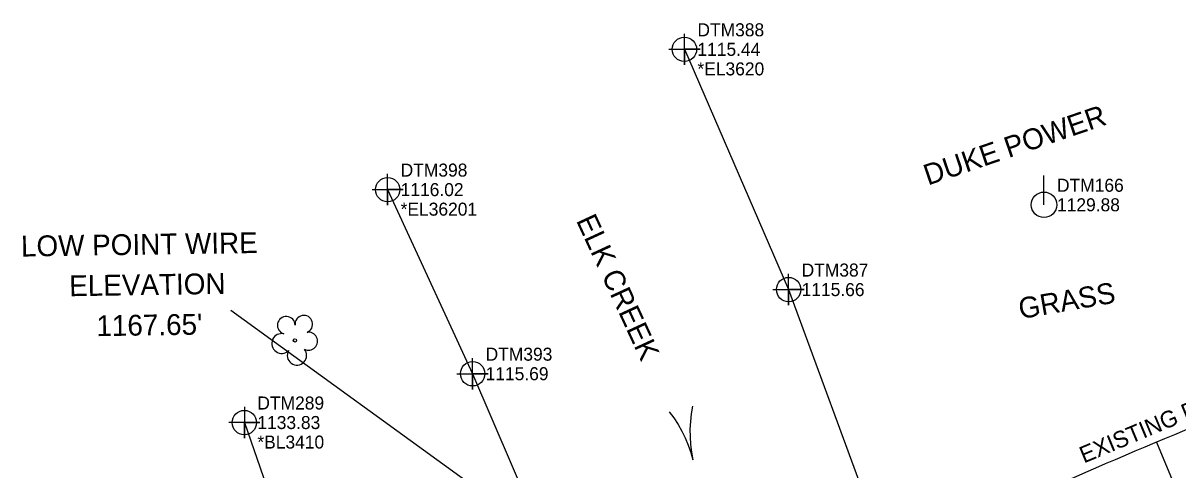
# Model space of a CAD drawing. Extents: x 1286007 to 1287145, y 857718 to 858514.
# Drawn here: x 1286461 to 1286682.8, y 858211.3 to 858297.1 of the extents above; entities that cross this region are included whole.
import ezdxf

# ---------------------------------------------------------------- set-up
doc = ezdxf.new("R2010")
doc.units = 0
for name, color, linetype in [('Exist Hydro Jurisdictional Stream or Body of Water', 7, 'Continuous'), ('Exist Hydro Jurisdictional Stream or Body of Water Text', 7, 'Continuous'), ('Exist Hydro Stream Flow Arrow CELL', 7, 'Continuous'), ('Exist Hydro Stream or Body of Water Cogo Comment', 7, 'Continuous'), ('Exist Hydro Stream or Body of Water Cogo Elevation', 7, 'Continuous'), ('Exist Hydro Stream or Body of Water Cogo Number', 7, 'Continuous'), ('Exist Hydro Stream or Body of Water Cogo Point CELL', 7, 'Continuous'), ('Exist Other Culture Fence Line', 7, 'Continuous'), ('Exist Other Culture Fence Line Cogo Comment', 7, 'Continuous'), ('Exist Other Culture Fence Line Cogo Elevation', 7, 'Continuous'), ('Exist Other Culture Fence Line Cogo Number', 7, 'Continuous'), ('Exist Other Culture Fence Line Cogo Point CELL', 7, 'Continuous'), ('Exist Right of Way Line', 7, 'Continuous'), ('Exist Right of Way Line Text', 7, 'Continuous'), ('Exist Right of Way Width CELL', 7, 'Continuous'), ('Exist Utilities Other Located Object Leader', 7, 'Continuous'), ('Exist Utilities Other Located Object Text', 7, 'Continuous'), ('Exist Utilities Power Joint Use Telephone Text', 7, 'Continuous'), ('Exist Utilities Power Pole CELL', 7, 'Continuous'), ('Exist Utilities Power Pole Cogo Elevation', 7, 'Continuous'), ('Exist Utilities Power Pole Cogo Number', 7, 'Continuous'), ('Exist Vegetation Tree CELL', 7, 'Continuous'), ('Exist Vegetation Tree Text', 7, 'Continuous')]:
    doc.layers.add(name, color=color, linetype=linetype)

msp = doc.modelspace()

# ---------------------------------------------------------------- linework, layer by layer
at = {"layer": 'Exist Hydro Jurisdictional Stream or Body of Water'}
for points in [[(1286588.04, 858292.08), (1286608.05, 858245.96), (1286624.22, 858201.93), (1286632.66, 858177.58)], [(1286531.04, 858265.15), (1286547.36, 858229.8), (1286577.59, 858159.31), (1286579.86, 858152.89)]]:
    msp.add_lwpolyline(points, dxfattribs=at)
at = {"layer": 'Exist Hydro Stream Flow Arrow CELL'}
msp.add_line((1286588.52, 858218.17), (1286588.52, 858218.17), dxfattribs=at)
for points in [[(1286585.14, 858222.5), (1286586.03, 858221.34), (1286586.81, 858220.06), (1286587.57, 858218.79), (1286588.2, 858217.49), (1286588.77, 858216.12), (1286589.27, 858214.71), (1286589.68, 858213.3)], [(1286589.59, 858223.56), (1286589.31, 858222.12), (1286589.19, 858220.63), (1286589.1, 858219.15), (1286589.12, 858217.71), (1286589.23, 858216.23), (1286589.42, 858214.74), (1286589.68, 858213.3)]]:
    msp.add_lwpolyline(points, dxfattribs=at)
at = {"layer": 'Exist Hydro Stream or Body of Water Cogo Point CELL'}
for points in [[(1286585.04, 858292.08), (1286591.04, 858292.08), (1286588.04, 858292.08), (1286588.04, 858289.08), (1286588.04, 858295.08)], [(1286528.04, 858265.15), (1286534.04, 858265.15), (1286531.04, 858265.15), (1286531.04, 858262.15), (1286531.04, 858268.15)], [(1286605.05, 858245.96), (1286611.05, 858245.96), (1286608.05, 858245.96), (1286608.05, 858242.96), (1286608.05, 858248.96)], [(1286544.36, 858229.8), (1286550.36, 858229.8), (1286547.36, 858229.8), (1286547.36, 858226.8), (1286547.36, 858232.8)]]:
    msp.add_lwpolyline(points, dxfattribs=at)
for centre in [(1286588.04, 858292.08), (1286531.04, 858265.15), (1286608.05, 858245.96), (1286547.36, 858229.8)]:
    msp.add_circle(centre, 2.34, dxfattribs=at)
at = {"layer": 'Exist Other Culture Fence Line'}
msp.add_lwpolyline([(1286503.52, 858220.43), (1286523.48, 858162.85), (1286555.61, 858144.3), (1286656.76, 858190.72)], dxfattribs=at)
at = {"layer": 'Exist Other Culture Fence Line Cogo Point CELL'}
msp.add_lwpolyline([(1286503.52, 858223.43), (1286503.52, 858217.43), (1286503.52, 858220.43), (1286506.52, 858220.43), (1286500.52, 858220.43)], dxfattribs=at)
msp.add_circle((1286503.52, 858220.43), 2.34, dxfattribs=at)
at = {"layer": 'Exist Right of Way Line'}
msp.add_arc((1287151.68, 857086.65), 1225, 111.95838, 115.04397, dxfattribs=at)
at = {"layer": 'Exist Right of Way Width CELL'}
msp.add_line((1286678.69, 858216.65), (1286684.01, 858203.93), dxfattribs=at)
at = {"layer": 'Exist Utilities Other Located Object Leader'}
msp.add_line((1286552.04, 858204.95), (1286500.93, 858241.96), dxfattribs=at)
at = {"layer": 'Exist Utilities Power Pole CELL'}
for q in [(1286657.1, 858267.87), (1286657.1, 858262.24)]:
    msp.add_line((1286657.1, 858262.24), q, dxfattribs=at)
msp.add_circle((1286657.1, 858262.24), 2.45, dxfattribs=at)
at = {"layer": 'Exist Vegetation Tree CELL'}
msp.add_line((1286513.24, 858236.2), (1286513.24, 858236.2), dxfattribs=at)
msp.add_circle((1286513.24, 858236.2), 0.326, dxfattribs=at)
for centre, radius, start, end in [((1286511.57, 858239.1), 1.7, 1.2822, 254.56), ((1286514.94, 858239.32), 1.69, 291.5671, 186.231), ((1286515.84, 858236.05), 1.73, 242.6636, 99.3457), ((1286510.69, 858235.61), 1.9, 77.1011, 314.1999), ((1286513.62, 858233.33), 1.86, 150.1651, 39.7134)]:
    msp.add_arc(centre, radius, start, end, dxfattribs=at)

# ---------------------------------------------------------------- texts
at = {"layer": 'Exist Hydro Jurisdictional Stream or Body of Water Text'}
msp.add_text('ELK CREEK', height=4, rotation=294.7842, dxfattribs=at).set_placement((1286567.18, 858259.24))
at = {"layer": 'Exist Hydro Stream or Body of Water Cogo Comment'}
for s, p in [('*EL3620', (1286590.54, 858287.08)), ('*EL36201', (1286533.54, 858260.15))]:
    msp.add_text(s, height=2.5, dxfattribs=at).set_placement(p)
at = {"layer": 'Exist Hydro Stream or Body of Water Cogo Elevation'}
for s, p in [('1115.44', (1286590.54, 858290.83)), ('1116.02', (1286533.54, 858263.9)), ('1115.66', (1286610.55, 858244.71)), ('1115.69', (1286549.86, 858228.56))]:
    msp.add_text(s, height=2.5, dxfattribs=at).set_placement(p)
at = {"layer": 'Exist Hydro Stream or Body of Water Cogo Number'}
for s, p in [('DTM388', (1286590.54, 858294.58)), ('DTM398', (1286533.54, 858267.65)), ('DTM387', (1286610.55, 858248.46)), ('DTM393', (1286549.86, 858232.31))]:
    msp.add_text(s, height=2.5, dxfattribs=at).set_placement(p)
at = {"layer": 'Exist Other Culture Fence Line Cogo Comment'}
msp.add_text('*BL3410', height=2.5, dxfattribs=at).set_placement((1286506.02, 858215.44))
at = {"layer": 'Exist Other Culture Fence Line Cogo Elevation'}
msp.add_text('1133.83', height=2.5, dxfattribs=at).set_placement((1286506.02, 858219.19))
at = {"layer": 'Exist Other Culture Fence Line Cogo Number'}
msp.add_text('DTM289', height=2.5, dxfattribs=at).set_placement((1286506.02, 858222.94))
at = {"layer": 'Exist Right of Way Line Text'}
msp.add_text('EXISTING R/W', height=3.2, rotation=22.6442, dxfattribs=at).set_placement((1286664.76, 858212.57))
at = {"layer": 'Exist Utilities Other Located Object Text'}
for s, p in [('LOW POINT WIRE ', (1286460.65, 858252.29)), ('ELEVATION', (1286469.91, 858244.68)), ("1167.65'", (1286475.13, 858237.01))]:
    msp.add_text(s, height=4, rotation=0.8742, dxfattribs=at).set_placement(p)
at = {"layer": 'Exist Utilities Power Joint Use Telephone Text'}
msp.add_text('DUKE POWER ', height=4, rotation=18.8209, dxfattribs=at).set_placement((1286634.81, 858265.92))
at = {"layer": 'Exist Utilities Power Pole Cogo Elevation'}
msp.add_text('1129.88', height=2.5, dxfattribs=at).set_placement((1286659.6, 858260.99))
at = {"layer": 'Exist Utilities Power Pole Cogo Number'}
msp.add_text('DTM166', height=2.5, dxfattribs=at).set_placement((1286659.6, 858264.74))
at = {"layer": 'Exist Vegetation Tree Text'}
msp.add_text('GRASS', height=4, rotation=9.844, dxfattribs=at).set_placement((1286652.59, 858240.29))

doc.saveas('drawing.dxf')
